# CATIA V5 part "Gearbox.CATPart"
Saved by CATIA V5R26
Part number: Gearbox
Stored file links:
  C:\Users\Safar Abadi\Desktop\Gearbox.CATPart

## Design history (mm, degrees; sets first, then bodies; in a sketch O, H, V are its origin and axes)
Body1 "Solid1" (main body)
  Solid1: solid without history
Body2 "Solid2"
  Solid2: solid without history
Body3 "Solid3"
  Solid3: solid without history
Body4 "Solid4"
  Solid4: solid without history
Body5 "Solid5"
  Solid5: solid without history
Body6 "Solid6"
  Solid6: solid without history
Body7 "Solid7"
  Solid7: solid without history
Body8 "Solid8"
  Solid8: solid without history
Body9 "Solid10"
  Solid9: solid without history
Body10 "Solid11"
  Solid10: solid without history
Body11 "Solid12"
  Solid11: solid without history
Body12 "Solid13"
  Solid12: solid without history
Body13 "Solid14"
  Solid13: solid without history
Body14 "Solid15"
  Solid14: solid without history
Body15 "Solid16"
  Solid15: solid without history
Body16 "Solid17"
  Solid16: solid without history
Body17 "Solid18"
  Solid17: solid without history
Body18 "Solid19"
  Solid18: solid without history
Body19 "Solid20"
  Solid19: solid without history
Body20 "Solid21"
  Solid20: solid without history
Body21 "Solid22"
  Solid21: solid without history
Body22 "Solid23"
  Solid22: solid without history
Body23 "Solid24"
  Solid23: solid without history
Body24 "Solid25"
  Solid24: solid without history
